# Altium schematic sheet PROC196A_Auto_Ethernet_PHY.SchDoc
size 431 x 279 mm; Date: Not shown in title block; ApprovedBy: Not shown in title block; CheckedBy: Not shown in title block; Author: Not shown in title block; CompanyName: Not shown in title block; Engineer: Not shown in title block; Organization: Not shown in title block; Address1: Not shown in title block; Address2: Not shown in title block; Address3: Not shown in title block; Address4: Not shown in title block; DocumentNumber: 14; Revision: Use project parameter SCH_Rev; SheetNumber: 14; SheetTotal: 25; PageSetup: Record=PageOptions¦CenterHorizontal=True¦CenterVertical=True¦PrintScale=1.00¦XCorrection=1.00¦YCorrection=1.00¦PrintKind=0¦BorderSize=5000000¦LeftOffset=0¦BottomOffset=0¦Orientation=2¦PaperLength=1000¦PaperWidth=1000¦Scale=100¦PaperSource=15¦PrintQuality=600¦MediaType=1¦DitherType=10¦PaperKind=Letter¦PrintScaleMode=1
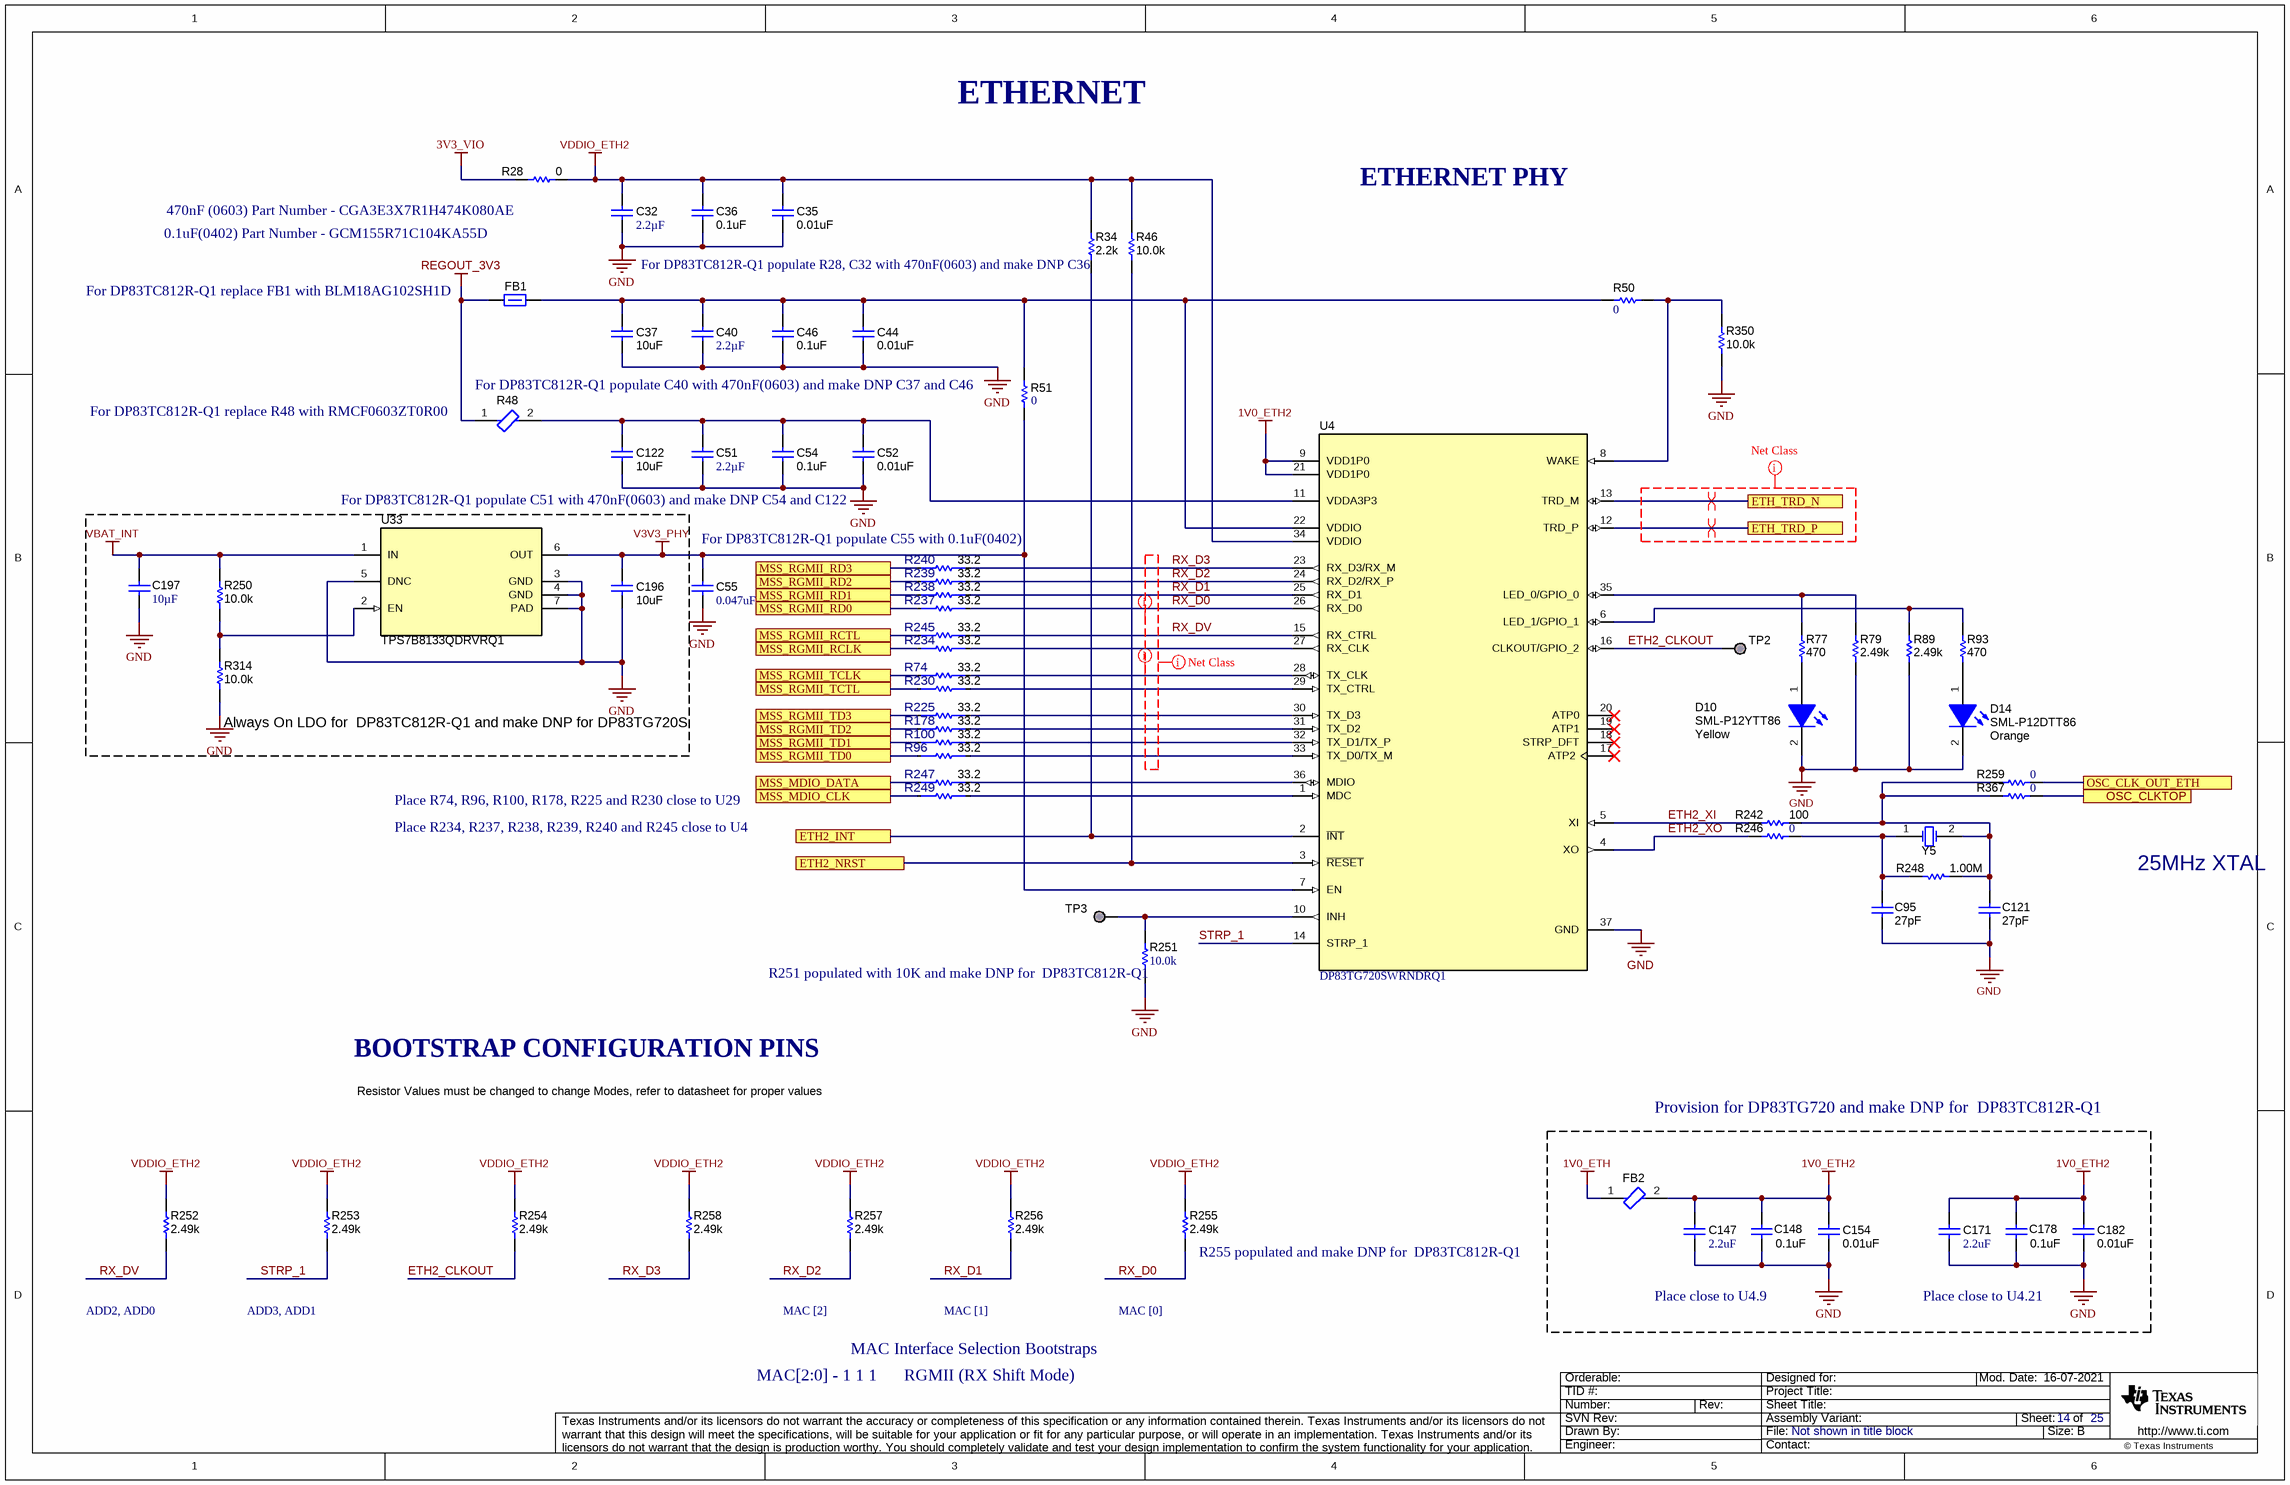
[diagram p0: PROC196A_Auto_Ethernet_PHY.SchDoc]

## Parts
C32  Cap_F: 2.2µF  [0603L]  (hidden comment: GCM188R70J225KE22D)
C35  ValueDisplayed: 0.01uF  [0402L]  (hidden comment: CGA2B3X7R1H103K050BB)
C36  ValueDisplayed: 0.1uF  [0402L]  (hidden comment: GCM155R71C104KA55D)
C37  ValueDisplayed: 10uF  [0805L]  (hidden comment: GCM21BR71A106KE22L)
C40  Cap_F: 2.2µF  [0603L]  (hidden comment: GCM188R70J225KE22D)
C44  ValueDisplayed: 0.01uF  [0402L]  (hidden comment: CGA2B3X7R1H103K050BB)
C46  ValueDisplayed: 0.1uF  [0402L]  (hidden comment: GCM155R71C104KA55D)
C51  Cap_F: 2.2µF  [0603L]  (hidden comment: GCM188R70J225KE22D)
C52  ValueDisplayed: 0.01uF  [0402L]  (hidden comment: CGA2B3X7R1H103K050BB)
C54  ValueDisplayed: 0.1uF  [0402L]  (hidden comment: GCM155R71C104KA55D)
C55  ValueDisplayed: 0.047uF  [0402L]  (hidden comment: GRM155R71E473KA88D)
C95  ValueDisplayed: 27pF  [0402L]  (hidden comment: GCM1555C1H270JA16D)
C121  ValueDisplayed: 27pF  [0402L]  (hidden comment: GCM1555C1H270JA16D)
C122  ValueDisplayed: 10uF  [0805L]  (hidden comment: GCM21BR71A106KE22L)
C147  ValueDisplayed: 2.2uF  [0603L]  (hidden comment: GCM188R70J225KE22D)
C148  ValueDisplayed: 0.1uF  [0402L]  (hidden comment: GCM155R71A104KA55D)
C154  ValueDisplayed: 0.01uF  [0402L]  (hidden comment: CGA2B3X7R1H103K050BB)
C171  ValueDisplayed: 2.2uF  [0603L]  (hidden comment: GCM188R70J225KE22D)
C178  ValueDisplayed: 0.1uF  [0402L]  (hidden comment: GCM155R71A104KA55D)
C182  ValueDisplayed: 0.01uF  [0402L]  (hidden comment: CGA2B3X7R1H103K050BB)
C196  ValueDisplayed: 10uF  [0805L]  (hidden comment: GCM21BR71A106KE22L)
C197  ValueDisplayed: 10µF  [1206L]  (hidden comment: CGA5L1X7R1H106K160AE)
D10  SML-P12YTT86  value Yellow  [LED_SMLP12_YELLOW]
D14  SML-P12DTT86  value Orange  [LED_SMLP12_ORANGE]
FB1  BLM18HE102SN1D  [0603]  (value not drawn)
FB2  BLM18KG601SH1  [FP-BLM18KG601SH1_0603 (1608 Metric)-MFG]  (value not drawn)
R28  ValueDisplayed: 0  [0603L]  (hidden comment: RMCF0603ZT0R00)
R34  ValueDisplayed: 2.2k  [0402L]  (hidden comment: CRCW04022K20JNED)
R46  ValueDisplayed: 10.0k  [0402L]  (hidden comment: CRCW040210K0FKED)
R48  BLM18KG601SH1  [FP-BLM18KG601SH1_0603 (1608 Metric)-MFG]  (value not drawn)
R50  ValueDisplayed: 0  [0402L]  (hidden comment: ERJ-2GE0R00X)
R51  ValueDisplayed: 0  [0402L]  (hidden comment: ERJ-2GE0R00X)
R74  Res_ohm: 33.2  [FP-ERJ-1GNF33R2C_0201-MFG]  (hidden comment: ERJ-1GNF33R2C)
R77  ValueDisplayed: 470  [0402L]  (hidden comment: ERJ-2RKF4700X)
R79  ValueDisplayed: 2.49k  [0402L]  (hidden comment: CRCW04022K49FKED)
R89  ValueDisplayed: 2.49k  [0402L]  (hidden comment: CRCW04022K49FKED)
R93  ValueDisplayed: 470  [0402L]  (hidden comment: ERJ-2RKF4700X)
R96  Res_ohm: 33.2  [FP-ERJ-1GNF33R2C_0201-MFG]  (hidden comment: ERJ-1GNF33R2C)
R100  Res_ohm: 33.2  [FP-ERJ-1GNF33R2C_0201-MFG]  (hidden comment: ERJ-1GNF33R2C)
R178  Res_ohm: 33.2  [FP-ERJ-1GNF33R2C_0201-MFG]  (hidden comment: ERJ-1GNF33R2C)
R225  Res_ohm: 33.2  [FP-ERJ-1GNF33R2C_0201-MFG]  (hidden comment: ERJ-1GNF33R2C)
R230  Res_ohm: 33.2  [FP-ERJ-1GNF33R2C_0201-MFG]  (hidden comment: ERJ-1GNF33R2C)
R234  Res_ohm: 33.2  [FP-ERJ-1GNF33R2C_0201-MFG]  (hidden comment: ERJ-1GNF33R2C)
R237  Res_ohm: 33.2  [FP-ERJ-1GNF33R2C_0201-MFG]  (hidden comment: ERJ-1GNF33R2C)
R238  Res_ohm: 33.2  [FP-ERJ-1GNF33R2C_0201-MFG]  (hidden comment: ERJ-1GNF33R2C)
R239  Res_ohm: 33.2  [FP-ERJ-1GNF33R2C_0201-MFG]  (hidden comment: ERJ-1GNF33R2C)
R240  Res_ohm: 33.2  [FP-ERJ-1GNF33R2C_0201-MFG]  (hidden comment: ERJ-1GNF33R2C)
R242  ValueDisplayed: 100  [0402L]  (hidden comment: ERJ-2GEJ101X)
R245  Res_ohm: 33.2  [FP-ERJ-1GNF33R2C_0201-MFG]  (hidden comment: ERJ-1GNF33R2C)
R246  ValueDisplayed: 0  [0402L]  (hidden comment: ERJ-2GE0R00X)
R247  Res_ohm: 33.2  [FP-ERJ-1GNF33R2C_0201-MFG]  (hidden comment: ERJ-1GNF33R2C)
R248  ValueDisplayed: 1.00M  [0603L]  (hidden comment: CRCW06031M00FKEA)
R249  Res_ohm: 33.2  [FP-ERJ-1GNF33R2C_0201-MFG]  (hidden comment: ERJ-1GNF33R2C)
R250  ValueDisplayed: 10.0k  [0402L]  (hidden comment: CRCW040210K0FKED)
R251  ValueDisplayed: 10.0k  [0402L]  (hidden comment: CRCW040210K0FKED)
R252  ValueDisplayed: 2.49k  [0402L]  (hidden comment: CRCW04022K49FKED)
R253  ValueDisplayed: 2.49k  [0402L]  (hidden comment: CRCW04022K49FKED)
R254  ValueDisplayed: 2.49k  [0402L]  (hidden comment: CRCW04022K49FKED)
R255  ValueDisplayed: 2.49k  [0402L]  (hidden comment: CRCW04022K49FKED)
R256  ValueDisplayed: 2.49k  [0402L]  (hidden comment: CRCW04022K49FKED)
R257  ValueDisplayed: 2.49k  [0402L]  (hidden comment: CRCW04022K49FKED)
R258  ValueDisplayed: 2.49k  [0402L]  (hidden comment: CRCW04022K49FKED)
R259  ValueDisplayed: 0  [0402L]  (hidden comment: ERJ-2GE0R00X)
R314  ValueDisplayed: 10.0k  [0402L]  (hidden comment: CRCW040210K0FKED)
R350  ValueDisplayed: 10.0k  [0402L]  (hidden comment: CRCW040210K0FKED)
R367  ValueDisplayed: 0  [0402L]  (hidden comment: ERJ-2GE0R00X)
TP2  TESTPOINT  [TP_25MIL-SMT]  (value not drawn)  (no BOM)
TP3  TESTPOINT  [TP_25MIL-SMT]  (value not drawn)  (no BOM)
U4  DP83TG720SWRNDRQ1  [RND0036A]
U33  TPS7B8133QDRVRQ1  [DRV0006A]
Y5  ABM3-25.000MHZ-D2W-T  [XTAL_ABM3]  (value not drawn)

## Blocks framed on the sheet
Always On LDO for  DP83TC812R-Q1 and make DNP for DP83TG720S: C196 C197 R250 R314 U33
Provision for DP83TG720 and make DNP for  DP83TC812R-Q1: C147 C148 C154 C171 C178 C182 FB2

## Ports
ETH2_INT, ETH2_NRST, ETH_TRD_N, ETH_TRD_P, MSS_MDIO_CLK, MSS_MDIO_DATA, MSS_RGMII_RCLK, MSS_RGMII_RCTL, MSS_RGMII_RD0, MSS_RGMII_RD1, MSS_RGMII_RD2, MSS_RGMII_RD3, MSS_RGMII_TCLK, MSS_RGMII_TCTL, MSS_RGMII_TD0, MSS_RGMII_TD1, MSS_RGMII_TD2, MSS_RGMII_TD3, OSC_CLK_OUT_ETH, OSC_CLKTOP

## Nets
1V0_ETH: FB2.1
1V0_ETH2: C147.1 C148.1 C154.1 C171.1 C178.1 C182.1 FB2.2 U4.9(VDD1P0) U4.21(VDD1P0)
3V3_VIO: R28.1
GND: C32.2 C35.2 C36.1 C37.2 C40.2 C44.2 C46.1 C51.2 C52.2 C54.1 C55.1 C95.2 C121.2 C122.2 C147.2 C148.2 C154.2 C171.2 C178.2 C182.2 C196.2 C197.2 D10.2(K) D14.2(K) R79.1 R89.2 R251.1 R314.1 R350.2 U4.37(GND) U33.3(GND) U33.4(GND) U33.5(DNC) U33.7(PAD)
REGOUT_3V3: FB1.1 R48.1
V3V3_PHY: C55.2 C196.1 R51.1 U4.7(EN) U33.6(OUT)
VBAT_INT: C197.1 R250.2 U33.1(IN)
VDDIO_ETH2: C32.1 C35.1 C36.2 R28.2 R34.1 R46.1 R252.2 R253.2 R254.2 R255.2 R256.2 R257.2 R258.2 U4.34(VDDIO)
ETH2_CLKOUT: R254.1 TP2.1 U4.16(CLKOUT/GPIO_2)
ETH2_INT: R34.2 U4.2(~{INT}) ; port ETH2_INT
ETH2_NRST: R46.2 U4.3(~{RESET}) ; port ETH2_NRST
ETH2_XI: R242.1 U4.5(XI)
ETH2_XO: R246.2 U4.4(XO)
ETH_TRD_N: U4.13(TRD_M) ; port ETH_TRD_N
ETH_TRD_P: U4.12(TRD_P) ; port ETH_TRD_P
MSS_MDIO_CLK: R249.1 ; port MSS_MDIO_CLK
MSS_MDIO_DATA: R247.1 ; port MSS_MDIO_DATA
MSS_RGMII_RCLK: R234.1 ; port MSS_RGMII_RCLK
MSS_RGMII_RCTL: R245.1 ; port MSS_RGMII_RCTL
MSS_RGMII_RD0: R237.1 ; port MSS_RGMII_RD0
MSS_RGMII_RD1: R238.1 ; port MSS_RGMII_RD1
MSS_RGMII_RD2: R239.1 ; port MSS_RGMII_RD2
MSS_RGMII_RD3: R240.1 ; port MSS_RGMII_RD3
MSS_RGMII_TCLK: R74.1 ; port MSS_RGMII_TCLK
MSS_RGMII_TCTL: R230.1 ; port MSS_RGMII_TCTL
MSS_RGMII_TD0: R96.1 ; port MSS_RGMII_TD0
MSS_RGMII_TD1: R100.1 ; port MSS_RGMII_TD1
MSS_RGMII_TD2: R178.1 ; port MSS_RGMII_TD2
MSS_RGMII_TD3: R225.1 ; port MSS_RGMII_TD3
OSC_CLK_OUT_ETH: R259.1 ; port OSC_CLK_OUT_ETH
OSC_CLKTOP: R367.1 ; port OSC_CLKTOP
RX_D0: R237.2 R255.1 U4.26(RX_D0)
RX_D1: R238.2 R256.1 U4.25(RX_D1)
RX_D2: R239.2 R257.1 U4.24(RX_D2/RX_P)
RX_D3: R240.2 R258.1 U4.23(RX_D3/RX_M)
RX_DV: R245.2 R252.1 U4.15(RX_CTRL)
STRP_1: R253.1 U4.14(STRP_1)
NetC37_1: C37.1 C40.1 C44.1 C46.2 FB1.2 R50.2 R51.2 U4.22(VDDIO)
NetC51_1: C51.1 C52.1 C54.2 C122.1 R48.2 U4.11(VDDA3P3)
NetC95_1: C95.1 R246.1 R248.2 Y5.1(OSC1)
NetC121_1: C121.1 R242.2 R248.1 R259.2 R367.2 Y5.2(OSC2)
NetD10_1: D10.1(A) R77.1
NetD14_1: D14.1(A) R93.1
NetR50_1: R50.1 R350.1 U4.8(WAKE)
NetR74_2: R74.2 U4.28(TX_CLK)
NetR77_2: R77.2 R79.2 U4.35(LED_0/GPIO_0)
NetR89_1: R89.1 R93.2 U4.6(LED_1/GPIO_1)
NetR96_2: R96.2 U4.33(TX_D0/TX_M)
NetR100_2: R100.2 U4.32(TX_D1/TX_P)
NetR178_2: R178.2 U4.31(TX_D2)
NetR225_2: R225.2 U4.30(TX_D3)
NetR230_2: R230.2 U4.29(TX_CTRL)
NetR234_2: R234.2 U4.27(RX_CLK)
NetR247_2: R247.2 U4.36(MDIO)
NetR249_2: R249.2 U4.1(MDC)
NetR250_1: R250.1 R314.2 U33.2(EN)
NetR251_2: R251.2 TP3.1 U4.10(INH)

Not connected (* = marked no-connect by the designer): U4 17(ATP2)* 18(STRP_DFT)* 19(ATP1)* 20(ATP0)*

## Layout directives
net class RGMII: (no net found under the mark), NetR74_2
differential pair: ETH_TRD_N, ETH_TRD_P

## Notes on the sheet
- ETHERNET
- (near R28) 470nF (0603) Part Number - CGA3E3X7R1H474K080AE
- ETHERNET PHY
- For DP83TC812R-Q1 replace FB1 with BLM18AG102SH1D
- 0.1uF(0402) Part Number - GCM155R71C104KA55D
- (near R34) For DP83TC812R-Q1 populate R28, C32 with 470nF(0603) and make DNP C36
- For DP83TC812R-Q1 replace R48 with RMCF0603ZT0R00
- For DP83TC812R-Q1 populate C40 with 470nF(0603) and make DNP C37 and C46
- For DP83TC812R-Q1 populate C51 with 470nF(0603) and make DNP C54 and C122
- For DP83TC812R-Q1 populate C55 with 0.1uF(0402)
- Place R74, R96, R100, R178, R225 and R230 close to U29
- Place R234, R237, R238, R239, R240 and R245 close to U4
- 25MHz XTAL
- (near R251) R251 populated with 10K and make DNP for  DP83TC812R-Q1
- BOOTSTRAP CONFIGURATION PINS
- Resistor Values must be changed to change Modes, refer to datasheet for proper values
- (near R255) R255 populated and make DNP for  DP83TC812R-Q1
- Place close to U4.9
- Place close to U4.21
- ADD2, ADD0
- ADD3, ADD1
- MAC [2]
- MAC Interface Selection Bootstraps
- MAC [1]
- MAC [0]
- MAC[2:0] - 1 1 1      RGMII (RX Shift Mode)

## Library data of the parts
C32 C40 C51 = CMP-0007134-5: CAP, CERM, 2.2 uF, 6.3 V, +/- 10%, X7R, AEC-Q200 Grade 1, 0603; Manufacturer: MuRata; TaMin_C: -55°C; Polarized: N; SizeAreaWB_mm2: 4.68; Value1: Unknown; U/M: EA; Value: 2.2uF; TaMax_C: 125°C; SizeZ_mm: 1; SizeX_mm: 1.6; SizeY_mm: 0.8; Cap_Case: 0603; Value2: 6.3V; SizeArea_mm2: 1.28; AEC Qualified: Y; AEC Category: Q200
C35 C44 C52 C154 C182 = CMP-0006324-2: CAP, CERM, 0.01 uF, 50 V, +/- 10%, X7R, AEC-Q200 Grade 1, 0402; Manufacturer: TDK; TaMin_C: -55°C; ESR_ohm: 0.333065; Polarized: N; SizeAreaWB_mm2: 3; Value1: 0.333065 ohm; U/M: EA; Value: 0.01uF; TaMax_C: 125°C; SizeZ_mm: 0.6; SizeX_mm: 1; SizeY_mm: 0.5; Cap_Case: 0402; Value2: 50V; CompType: Capacitor; AEC Qualified: Y; Cap_F: 10nF; IRMS_A: 323.373mA; AEC Category: Q200
C36 C46 C54 = CMP-0006351-2: CAP, CERM, 0.1 uF, 16 V, +/- 10%, X7R, 0402; Manufacturer: MuRata; TaMin_C: -55°C; Polarized: N; SizeAreaWB_mm2: 3; Value1: Unknown; U/M: EA; Value: 0.1uF; TaMax_C: 125°C; SizeZ_mm: 0.6; SizeX_mm: 1; SizeY_mm: 0.5; Cap_Case: 0402; Value2: 16V; CompType: Capacitor; Cap_F: 100nF; AEC Category: Q200
C37 C122 C196 = CMP-0008017-2: CAP, CERM, 10 uF, 10 V, +/- 10%, X7R, 0805; Manufacturer: MuRata; TaMin_C: -55°C; Polarized: N; SizeAreaWB_mm2: 6.75; Value1: Unknown; U/M: EA; Value: 10uF; TaMax_C: 125°C; SizeZ_mm: 1.45; SizeX_mm: 2; SizeY_mm: 1.25; Cap_Case: 0805; Value2: 10V; SizeArea_mm2: 2.5; CompType: Capacitor; Cap_F: 10µF; AEC Category: Q200
C55 = CMP-0006669-2: CAP, CERM, 0.047 uF, 25 V, +/- 10%, X7R, 0402; Manufacturer: MuRata; TaMin_C: -55°C; Polarized: N; SizeAreaWB_mm2: 3; Value1: Unknown; U/M: EA; TaMax_C: 125°C; SizeZ_mm: 0.6; SizeX_mm: 1; SizeY_mm: 0.5; Cap_Case: 0402; Value2: 25V; Cap_F: 47nF; AEC Category: Q200
C95 C121 = CMP-0860920-1: CAP, CERM, 27 pF, 50 V,+/- 5%, C0G/NP0, AEC-Q200 Grade 1, 0402; Manufacturer: MuRata; AEC Grade: 1; SizeZ_mm: 0.6; U/M: EA; Value: 27pF; SizeY_mm: 0.5; TaMax_C: 125°C; Polarized: N; AEC Qualified: Y; Cap_Case: 0402; AEC Category: Q200; Value2: 50V; SizeAreaWB_mm2: 3; TaMin_C: -55°C
C147 C171 = CMP-0007134-5: CAP, CERM, 2.2 uF, 6.3 V, +/- 10%, X7R, AEC-Q200 Grade 1, 0603; Manufacturer: MuRata; TaMin_C: -55°C; Polarized: N; SizeAreaWB_mm2: 4.68; Value1: Unknown; U/M: EA; Value: 2.2uF; TaMax_C: 125°C; SizeZ_mm: 1; SizeX_mm: 1.6; SizeY_mm: 0.8; Cap_Case: 0603; Value2: 6.3V; SizeArea_mm2: 1.28; AEC Qualified: Y; Cap_F: 2.2µF; AEC Category: Q200
C148 C178 = CMP-0006350-2: CAP, CERM, 0.1 uF, 10 V, +/- 10%, X7R, AEC-Q200 Grade 1, 0402; Manufacturer: MuRata; TaMin_C: -55°C; Polarized: N; SizeAreaWB_mm2: 3; Value1: Unknown; U/M: EA; Value: 0.1uF; TaMax_C: 125°C; SizeZ_mm: 0.6; SizeX_mm: 1; SizeY_mm: 0.5; Cap_Case: 0402; Value2: 10V; AEC Qualified: Y; Cap_F: 100nF; AEC Category: Q200
C197 = CMP-0860898-1: CAP, CERM, 10 µF, 50 V,+/- 10%, X7R, AEC-Q200 Grade 1, 1206; Manufacturer: TDK; SizeY_mm: 1.6; AEC Category: Q200; U/M: EA; Polarized: N; VDC_V: 50V; TaMin_C: -55°C; TaMax_C: 125°C; SizeX_mm: 3.2; AEC Qualified: Y; SizeZ_mm: 1.35; Value: 10uF; SizeArea_mm2: 5.12; Cap_Case: 1206; SizeAreaWB_mm2: 10.92; AEC Grade: 1
D10 = CMP-0002839-2: LED, Yellow, SMD; Manufacturer: Rohm; Vf_V: 2.1V; Tjmax_C: 85°C; Value1: W; Type: InGaN; Io_A: 20mA
D14 = CMP-0002841-1: LED, Orange, SMD; Manufacturer: Rohm; Io_A: 20mA; Tjmax_C: 85°C; Value1: W; U/M: EA; Vf_V: 2.1V; Type: InGaN
FB1 = CMP-0003348-2: Ferrite Bead, 1000 ohm @ 100 MHz, 0.6 A, 0603; Manufacturer: MuRata; Ztyp@1GHz_Ohm: 1k; SizeAreaWB_mm2: 4.68; DCR_ohm: 3.5d; Value1: 0.35 ohm; Imax_A: 6dA; SizeZ_mm: 1; SizeX_mm: 1.6; SizeY_mm: 0.8; Value2: 0.6A; SizeArea_mm2: 1.28
FB2 R48 = CMP-0089848-1: 600 Ohms @ 100MHz 1 Power Line Ferrite Bead 0603 (1608 Metric) 1.3A 150mOhm; Manufacturer: Murata; Tolerance_%: 25%; SizeZ_mm: 0.95mm; Impedance At Frequency: 600Ω @ 100MHz; AEC Qualified: Yes; AEC Grade: Grade 1; DCR_ohm: 1.5d
R28 = CMP-0023343-3: RES, 0, 1%, 0.1 W, AEC-Q200 Grade 0, 0603; Manufacturer: Stackpole Electronics Inc; Power_W: 100mW; TempCo: ppm/C; U/M: EA; Value: 0; SizeX_mm: 1.6; SizeY_mm: 0.8; SizeZ_mm: 1; Value2: 0.1W; SizeArea_mm2: 1.28; AEC Qualified: Y; AEC Category: Q200
R34 = CMP-0026890-5: RES, 2.2 k, 5%, 0.063 W, AEC-Q200 Grade 0, 0402; Manufacturer: Vishay-Dale; Power_W: 63mW; TempCo: 200 ppm/C; Value_Code: 2k20; Value: 2.2k; EIA_Code: E24; SizeX_mm: 1; SizeY_mm: 0.5; SizeZ_mm: 0.6; Value2: 0.063W; AEC Qualified: Y; VDC_V: 50V; AEC Category: Q200; AEC Grade: 0
R46 R350 = CMP-0025958-3: RES, 10.0 k, 1%, 0.063 W, AEC-Q200 Grade 0, 0402; Manufacturer: Vishay-Dale; Power_W: 63mW; TempCo: 100 ppm/C; Value_Code: 10k0; Value: 10.0k; EIA_Code: E96; Res_ohm: 10k; SizeX_mm: 1; SizeY_mm: 0.5; SizeZ_mm: 0.6; Value2: 0.063W; CompType: Resistor; AEC Qualified: Y; VDC_V: 50V; AEC Category: Q200; AEC Grade: 0
R50 R51 R246 R259 R367 = CMP-0026992-3: RES, 0, 5%, 0.1 W, AEC-Q200 Grade 0, 0402; Manufacturer: Panasonic; Power_W: 100mW; TempCo: 600 ppm/C; Value_Code: 0000; Value: 0; EIA_Code: E24; SizeX_mm: 1; SizeY_mm: 0.5; SizeZ_mm: 0.6; Value2: 0.1W; AEC Qualified: Y; VDC_V: 50V; AEC Category: Q200; SizeAreaWB_mm2: 3
R74 R96 R100 R178 R225 R230 R234 R237-R240 R245 R247 R249 = CMP-0089575-2: Res Thick Film 0201 33.2 Ohm 1% 0.05W(1/20W) ±200ppm/C Pad SMD Automotive T/R; Manufacturer: Panasonic; TempCo: 200ppm/°C; VDC_V: 25V; AEC Qualified: Yes; SizeZ_mm: 0.26mm; Power_W: 50mW; AEC Grade: Grade 1; Value: 33.2
R77 R93 = CMP-0026699-1: RES, 470, 1%, 0.1 W, AEC-Q200 Grade 0, 0402; Manufacturer: Panasonic; Power_W: 100mW; TempCo: 100 ppm/C; Value_Code: 470R; U/M: EA; Value: 470; SizeX_mm: 1; SizeY_mm: 0.5; SizeZ_mm: 0.6; Value2: 0.1W; AEC Qualified: Y; VDC_V: 50V; AEC Grade: 0; AEC Category: Q200
R79 R89 R252-R258 = CMP-0026237-2: RES, 2.49 k, 1%, 0.063 W, AEC-Q200 Grade 0, 0402; Manufacturer: Vishay-Dale; Power_W: 63mW; TempCo: 100 ppm/C; Value_Code: 2k49; Value: 2.49k; EIA_Code: E96; SizeX_mm: 1; SizeY_mm: 0.5; SizeZ_mm: 0.6; Value2: 0.063W; AEC Qualified: Y; VDC_V: 50V; AEC Category: Q200; AEC Grade: 0
R242 = CMP-0026993-2: RES, 100, 5%, 0.1 W, AEC-Q200 Grade 0, 0402; Manufacturer: Panasonic; Power_W: 100mW; TempCo: 200 ppm/C; Value_Code: 100R; U/M: EA; Value: 100; EIA_Code: E24; SizeX_mm: 1; SizeY_mm: 0.5; SizeZ_mm: 0.6; Value2: 0.1W; AEC Qualified: Y; AEC Grade: 0; AEC Category: Q200
R248 = CMP-0022138-4: RES, 1.00 M, 1%, 0.1 W, AEC-Q200 Grade 0, 0603; Manufacturer: Vishay-Dale; Power_W: 100mW; TempCo: 100 ppm/C; Value_Code: 1M00; Value: 1.00Meg; EIA_Code: E96; Res_ohm: 1M; SizeX_mm: 1.6; SizeY_mm: 0.8; SizeZ_mm: 1; Value2: 0.1W; SizeArea_mm2: 1.28; AEC Qualified: Y; VDC_V: 75V; AEC Category: Q200; AEC Grade: 0
R250 R251 R314 = CMP-0025958-3: RES, 10.0 k, 1%, 0.063 W, AEC-Q200 Grade 0, 0402; Manufacturer: Vishay-Dale; Power_W: 63mW; TempCo: 100 ppm/C; Value_Code: 10k0; Value: 10.0k; EIA_Code: E96; Res_ohm: 10k; SizeX_mm: 1; SizeY_mm: 0.5; SizeZ_mm: 0.6; Value2: 0.063W; AEC Qualified: Y; VDC_V: 50V; AEC Category: Q200; AEC Grade: 0
TP2 TP3 = CMP-0078143-3: TEST POINT.  No entry in BOM.
U4 = CMP-0085268-1: Low Power Auto PHY 1000BASE-T1 Automotive Ethernet Physical Layer Transceiver, RND0036A (VQFNP-36); Manufacturer: Texas Instruments; Alternate PartNumber: DP83TG720SWRNDTQ1; SizeZ_mm: 0.9; AEC Qualified: Y; AEC Category: Q200; CompType: IC; SizeArea_mm2: 36; SizeAreaWB_mm2: 64; SizeX_mm: 6
U33 = CMP-0860463-1: Automotive 150-mA high-voltage ultra-low-IQ low-dropout (LDO) linear regulator, DRV0006A (WSON-6); Alternate Manufacturer: Texas Instruments; AEC Qualified: Y; SizeY_mm: 2; SizeZ_mm: 0.8; AEC Category: Q200; CompType: IC; SizeArea_mm2: 4; SizeAreaWB_mm2: 9
Y5 = CMP-0004614-3: Crystal, 25 MHz, 18 pF, SMD; Manufacturer: Abracon Corporation; TaMax_C: 85°C; TaMin_C: -40°C; Frequency Stability: +/-25ppm; Frequency_Fixed: 25MHz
